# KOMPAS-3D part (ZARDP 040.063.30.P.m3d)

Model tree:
1. Плоскость XY
2. Плоскость ZX
3. Плоскость ZY
4. Ось X
5. Ось Y
6. Ось Z
7. Начало координат
8. Булева операция:1
9. Булева операция:2
10. Булева операция:3
11. Булева операция:4
12. Булева операция:5
13. Булева операция:6
